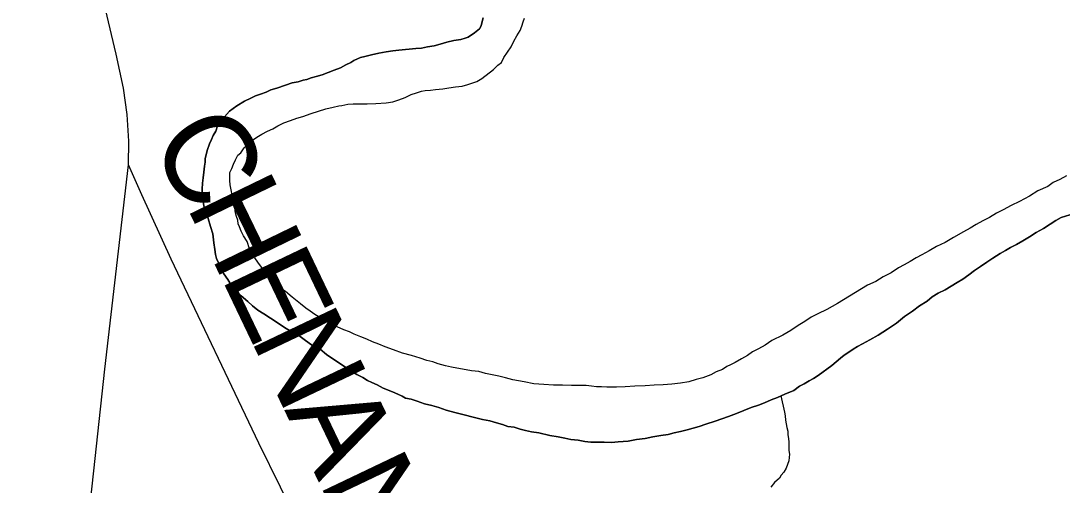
# Model space of a CAD drawing. Extents: x 0 to 34, y 0 to 22.
# Drawn here: x 4.269 to 4.921, y 16.776 to 17.067 of the extents above; entities that cross this region are included whole.
import ezdxf

# ---------------------------------------------------------------- set-up
doc = ezdxf.new("R2010")
doc.units = 0
for name, color, linetype in [('GM_X_Major_River', 7, 'Continuous'), ('GM_X_Minor_River', 7, 'Continuous'), ('GM_X_State_Route', 7, 'Continuous'), ('GM_X_Township_Road', 7, 'Continuous'), ('GM_X_Township_Road_Text', 7, 'Continuous')]:
    doc.layers.add(name, color=color, linetype=linetype)

msp = doc.modelspace()

# ---------------------------------------------------------------- linework, layer by layer
at = {"layer": 'GM_X_Major_River'}
for points in [[(4.55831, 17.06894), (4.55751, 17.06591), (4.55711, 17.06401), (4.55595, 17.06213), (4.55287, 17.05951), (4.54904, 17.05689), (4.54713, 17.05615), (4.54446, 17.05542), (4.53989, 17.05472), (4.5357, 17.05362), (4.5315, 17.05254), (4.52769, 17.05144), (4.5235, 17.05073), (4.51969, 17.05001), (4.51626, 17.04967), (4.50561, 17.04866), (4.5018, 17.04833), (4.49761, 17.04762), (4.49304, 17.04691), (4.48847, 17.04582), (4.48427, 17.04473), (4.4816, 17.044), (4.47969, 17.04326), (4.4774, 17.04215), (4.47548, 17.04104), (4.47243, 17.03955), (4.46898, 17.03769), (4.46516, 17.03622), (4.46134, 17.03474), (4.45752, 17.03326), (4.45371, 17.03217), (4.45066, 17.03144), (4.44798, 17.03034), (4.4457, 17.02998), (4.44265, 17.02888), (4.43884, 17.02817), (4.43464, 17.02669), (4.42929, 17.02486), (4.42548, 17.02376), (4.42242, 17.02228), (4.41898, 17.02118), (4.41593, 17.02007), (4.41287, 17.01859), (4.40905, 17.01673), (4.40407, 17.01375), (4.39947, 17.01039), (4.39639, 17.007), (4.39445, 17.00398), (4.39214, 17.00135), (4.39096, 16.99794), (4.3894, 16.9953), (4.38823, 16.99265), (4.38706, 16.99001), (4.38549, 16.98584), (4.38508, 16.98395), (4.38429, 16.98091), (4.38426, 16.97863), (4.38385, 16.97598), (4.38342, 16.97218), (4.383, 16.96877), (4.38258, 16.96535), (4.38254, 16.96155), (4.3825, 16.95851), (4.38355, 16.95127), (4.38465, 16.94746), (4.38612, 16.94326), (4.38758, 16.9383), (4.38904, 16.93372), (4.38973, 16.92801), (4.39044, 16.92382), (4.39079, 16.92078), (4.39151, 16.91811), (4.39262, 16.91543), (4.3941, 16.912), (4.39596, 16.90855), (4.39858, 16.9051)], [(4.39858, 16.9051), (4.39596, 16.90855), (4.3941, 16.912), (4.39262, 16.91543), (4.39151, 16.91811), (4.39079, 16.92078), (4.39044, 16.92382), (4.38973, 16.92801), (4.38904, 16.93372), (4.38758, 16.9383), (4.38612, 16.94326), (4.38465, 16.94746), (4.38355, 16.95127), (4.3825, 16.95851), (4.38254, 16.96155), (4.38258, 16.96535), (4.383, 16.96877), (4.38342, 16.97218), (4.38385, 16.97598), (4.38426, 16.97863), (4.38429, 16.98091), (4.38508, 16.98395), (4.38549, 16.98584), (4.38706, 16.99001), (4.38823, 16.99265), (4.3894, 16.9953), (4.39096, 16.99794), (4.39214, 17.00135), (4.39445, 17.00398), (4.39639, 17.007), (4.39947, 17.01039), (4.40407, 17.01375), (4.40905, 17.01673), (4.41287, 17.01859), (4.41593, 17.02007), (4.41898, 17.02118), (4.42242, 17.02228), (4.42548, 17.02376), (4.42929, 17.02486), (4.43464, 17.02669), (4.43884, 17.02817), (4.44265, 17.02888), (4.4457, 17.02998), (4.44798, 17.03034), (4.45066, 17.03144), (4.45371, 17.03217), (4.45752, 17.03326), (4.46134, 17.03474), (4.46516, 17.03622), (4.46898, 17.03769), (4.47243, 17.03955), (4.47548, 17.04104), (4.4774, 17.04215), (4.47969, 17.04326), (4.4816, 17.044), (4.48427, 17.04473), (4.48847, 17.04582), (4.49304, 17.04691), (4.49761, 17.04762), (4.5018, 17.04833), (4.50561, 17.04866), (4.51626, 17.04967), (4.51969, 17.05001), (4.5235, 17.05073), (4.52769, 17.05144), (4.5315, 17.05254), (4.5357, 17.05362), (4.53989, 17.05472), (4.54446, 17.05542), (4.54713, 17.05615), (4.54904, 17.05689), (4.55287, 17.05951), (4.55595, 17.06213), (4.55711, 17.06401), (4.55751, 17.06591), (4.55831, 17.06894)], [(4.51326, 17.02082), (4.51669, 17.02192), (4.51974, 17.02302), (4.52203, 17.02338), (4.52545, 17.02372), (4.5285, 17.02406), (4.53306, 17.02439), (4.53687, 17.0251), (4.54106, 17.02581), (4.54525, 17.02614), (4.54868, 17.02724), (4.55135, 17.02797), (4.55441, 17.02908), (4.55747, 17.03094), (4.56476, 17.03655), (4.56745, 17.03919), (4.56976, 17.04106), (4.57132, 17.04408), (4.57364, 17.04747), (4.57596, 17.05087), (4.57752, 17.05427), (4.57946, 17.05767), (4.5814, 17.06107), (4.58258, 17.06371), (4.58337, 17.06637), (4.58415, 17.06864)], [(4.51326, 17.02082), (4.51669, 17.02192), (4.51974, 17.02302), (4.52203, 17.02338), (4.52545, 17.02372), (4.5285, 17.02406), (4.53306, 17.02439), (4.53687, 17.0251), (4.54106, 17.02581), (4.54525, 17.02614), (4.54868, 17.02724), (4.55135, 17.02797), (4.55441, 17.02908), (4.55747, 17.03094), (4.56476, 17.03655), (4.56745, 17.03919), (4.56976, 17.04106), (4.57132, 17.04408), (4.57364, 17.04747), (4.57596, 17.05087), (4.57752, 17.05427), (4.57946, 17.05767), (4.5814, 17.06107), (4.58258, 17.06371), (4.58337, 17.06637), (4.58415, 17.06864)], [(4.62928, 16.83774), (4.62624, 16.83816), (4.62282, 16.83858), (4.61864, 16.83863), (4.6137, 16.83869), (4.608, 16.83875), (4.6023, 16.83882), (4.59622, 16.83927), (4.59015, 16.83973), (4.58408, 16.84094), (4.57687, 16.84216), (4.57232, 16.84336), (4.56815, 16.84455), (4.56398, 16.84536), (4.55981, 16.84617), (4.55564, 16.84736), (4.55109, 16.84779), (4.53857, 16.85022), (4.53478, 16.85103), (4.53023, 16.85222), (4.52683, 16.8534), (4.52303, 16.85421), (4.51887, 16.85578), (4.51357, 16.85736), (4.50789, 16.85895), (4.50221, 16.86092), (4.49691, 16.86288), (4.49313, 16.86444), (4.48897, 16.86601), (4.48556, 16.86758), (4.48178, 16.86914), (4.47762, 16.87071), (4.47459, 16.87227), (4.47119, 16.87345), (4.46703, 16.8754), (4.46287, 16.87735), (4.45909, 16.87929), (4.45608, 16.88123), (4.45306, 16.88317), (4.45004, 16.8851), (4.4474, 16.88704), (4.44401, 16.88974), (4.43874, 16.89398), (4.4346, 16.89745), (4.43084, 16.90092), (4.42746, 16.904), (4.42446, 16.90707), (4.42183, 16.91015), (4.41958, 16.91283), (4.41734, 16.9159), (4.41547, 16.91858), (4.41398, 16.92126), (4.41212, 16.92433), (4.41065, 16.9289), (4.40841, 16.93235), (4.40693, 16.93541), (4.40582, 16.93808), (4.40508, 16.94), (4.40473, 16.94228), (4.404, 16.94457), (4.40326, 16.94686), (4.40292, 16.9499), (4.4022, 16.95295), (4.40148, 16.95638), (4.40077, 16.96019), (4.40005, 16.96438), (4.39971, 16.96705), (4.39977, 16.97199), (4.40094, 16.97464), (4.40211, 16.97728), (4.40328, 16.97993), (4.40484, 16.98295), (4.40676, 16.98445), (4.40869, 16.98747), (4.41062, 16.98935), (4.41331, 16.99198), (4.41676, 16.99421), (4.41982, 16.99608), (4.42327, 16.99794), (4.42671, 16.99942), (4.42977, 17.00128), (4.43359, 17.00314), (4.43779, 17.00461), (4.44161, 17.00608), (4.44543, 17.00718), (4.45077, 17.00902), (4.45535, 17.01048), (4.45993, 17.01195), (4.4645, 17.01304), (4.46793, 17.01376), (4.46984, 17.01411), (4.47365, 17.01483), (4.47707, 17.01517), (4.48126, 17.01512), (4.48582, 17.01506), (4.49114, 17.01538), (4.49761, 17.01568), (4.5018, 17.01639), (4.50561, 17.01749), (4.50943, 17.01897), (4.51326, 17.02082)], [(4.62928, 16.83774), (4.62624, 16.83816), (4.62282, 16.83858), (4.61864, 16.83863), (4.6137, 16.83869), (4.608, 16.83875), (4.6023, 16.83882), (4.59622, 16.83927), (4.59015, 16.83973), (4.58408, 16.84094), (4.57687, 16.84216), (4.57232, 16.84336), (4.56815, 16.84455), (4.56398, 16.84536), (4.55981, 16.84617), (4.55564, 16.84736), (4.55109, 16.84779), (4.53857, 16.85022), (4.53478, 16.85103), (4.53023, 16.85222), (4.52683, 16.8534), (4.52303, 16.85421), (4.51887, 16.85578), (4.51357, 16.85736), (4.50789, 16.85895), (4.50221, 16.86092), (4.49691, 16.86288), (4.49313, 16.86444), (4.48897, 16.86601), (4.48556, 16.86758), (4.48178, 16.86914), (4.47762, 16.87071), (4.47459, 16.87227), (4.47119, 16.87345), (4.46703, 16.8754), (4.46287, 16.87735), (4.45909, 16.87929), (4.45608, 16.88123), (4.45306, 16.88317), (4.45004, 16.8851), (4.4474, 16.88704), (4.44401, 16.88974), (4.43874, 16.89398), (4.4346, 16.89745), (4.43084, 16.90092), (4.42746, 16.904), (4.42446, 16.90707), (4.42183, 16.91015), (4.41958, 16.91283), (4.41734, 16.9159), (4.41547, 16.91858), (4.41398, 16.92126), (4.41212, 16.92433), (4.41065, 16.9289), (4.40841, 16.93235), (4.40693, 16.93541), (4.40582, 16.93808), (4.40508, 16.94), (4.40473, 16.94228), (4.404, 16.94457), (4.40326, 16.94686), (4.40292, 16.9499), (4.4022, 16.95295), (4.40148, 16.95638), (4.40077, 16.96019), (4.40005, 16.96438), (4.39971, 16.96705), (4.39977, 16.97199), (4.40094, 16.97464), (4.40211, 16.97728), (4.40328, 16.97993), (4.40484, 16.98295), (4.40676, 16.98445), (4.40869, 16.98747), (4.41062, 16.98935), (4.41331, 16.99198), (4.41676, 16.99421), (4.41982, 16.99608), (4.42327, 16.99794), (4.42671, 16.99942), (4.42977, 17.00128), (4.43359, 17.00314), (4.43779, 17.00461), (4.44161, 17.00608), (4.44543, 17.00718), (4.45077, 17.00902), (4.45535, 17.01048), (4.45993, 17.01195), (4.4645, 17.01304), (4.46793, 17.01376), (4.46984, 17.01411), (4.47365, 17.01483), (4.47707, 17.01517), (4.48126, 17.01512), (4.48582, 17.01506), (4.49114, 17.01538), (4.49761, 17.01568), (4.5018, 17.01639), (4.50561, 17.01749), (4.50943, 17.01897), (4.51326, 17.02082)], [(4.92357, 16.96996), (4.91936, 16.96773), (4.91516, 16.96588), (4.91171, 16.96326), (4.90559, 16.96067), (4.90023, 16.95731), (4.89411, 16.95396), (4.88875, 16.95137), (4.88378, 16.94876), (4.87957, 16.94653), (4.87536, 16.94392), (4.87115, 16.94169), (4.86694, 16.93946), (4.86311, 16.93723), (4.85891, 16.93499), (4.85278, 16.93126), (4.84742, 16.92829), (4.84207, 16.92569), (4.83747, 16.92308), (4.83288, 16.92048), (4.82944, 16.91862), (4.82561, 16.91638), (4.82178, 16.91415), (4.81834, 16.91229), (4.81374, 16.9093), (4.80877, 16.9067), (4.80417, 16.90371), (4.79882, 16.90149), (4.78006, 16.88993), (4.77355, 16.88621), (4.76782, 16.88362), (4.76361, 16.88139), (4.75977, 16.87877), (4.75556, 16.87616), (4.75096, 16.87317), (4.74599, 16.87019), (4.7391, 16.86685), (4.73489, 16.86386), (4.73068, 16.86163), (4.72685, 16.85977), (4.72379, 16.85753), (4.71996, 16.85529), (4.71613, 16.85306), (4.71307, 16.85157), (4.71078, 16.85046), (4.70809, 16.84859), (4.70427, 16.84712), (4.70083, 16.84526), (4.69587, 16.84342), (4.69167, 16.84232), (4.68709, 16.84086), (4.68176, 16.84016), (4.67643, 16.83946), (4.67111, 16.83915), (4.6654, 16.83883), (4.6597, 16.83852), (4.65323, 16.83822), (4.64714, 16.83791), (4.64182, 16.83759), (4.63574, 16.83766), (4.63231, 16.83771), (4.62928, 16.83774)], [(4.92357, 16.96996), (4.91936, 16.96773), (4.91516, 16.96588), (4.91171, 16.96326), (4.90559, 16.96067), (4.90023, 16.95731), (4.89411, 16.95396), (4.88875, 16.95137), (4.88378, 16.94876), (4.87957, 16.94653), (4.87536, 16.94392), (4.87115, 16.94169), (4.86694, 16.93946), (4.86311, 16.93723), (4.85891, 16.93499), (4.85278, 16.93126), (4.84742, 16.92829), (4.84207, 16.92569), (4.83747, 16.92308), (4.83288, 16.92048), (4.82944, 16.91862), (4.82561, 16.91638), (4.82178, 16.91415), (4.81834, 16.91229), (4.81374, 16.9093), (4.80877, 16.9067), (4.80417, 16.90371), (4.79882, 16.90149), (4.78006, 16.88993), (4.77355, 16.88621), (4.76782, 16.88362), (4.76361, 16.88139), (4.75977, 16.87877), (4.75556, 16.87616), (4.75096, 16.87317), (4.74599, 16.87019), (4.7391, 16.86685), (4.73489, 16.86386), (4.73068, 16.86163), (4.72685, 16.85977), (4.72379, 16.85753), (4.71996, 16.85529), (4.71613, 16.85306), (4.71307, 16.85157), (4.71078, 16.85046), (4.70809, 16.84859), (4.70427, 16.84712), (4.70083, 16.84526), (4.69587, 16.84342), (4.69167, 16.84232), (4.68709, 16.84086), (4.68176, 16.84016), (4.67643, 16.83946), (4.67111, 16.83915), (4.6654, 16.83883), (4.6597, 16.83852), (4.65323, 16.83822), (4.64714, 16.83791), (4.64182, 16.83759), (4.63574, 16.83766), (4.63231, 16.83771), (4.62928, 16.83774)], [(4.82215, 16.88183), (4.82714, 16.88519), (4.83136, 16.88856), (4.83634, 16.89155), (4.83941, 16.89417), (4.84324, 16.8964), (4.84745, 16.89864), (4.85127, 16.90087), (4.8551, 16.90311), (4.85855, 16.90535), (4.86238, 16.90796), (4.86584, 16.91058), (4.86967, 16.9132), (4.8735, 16.91581), (4.87733, 16.91843), (4.88193, 16.92141), (4.88537, 16.92328), (4.88844, 16.92514), (4.89226, 16.927), (4.89609, 16.92923), (4.9003, 16.93184), (4.90452, 16.93445), (4.90911, 16.93706), (4.91332, 16.93967), (4.91677, 16.94191), (4.92021, 16.94377), (4.92556, 16.94561)], [(4.92556, 16.94561), (4.92021, 16.94377), (4.91677, 16.94191), (4.91332, 16.93967), (4.90911, 16.93706), (4.90452, 16.93445), (4.9003, 16.93184), (4.89609, 16.92923), (4.89226, 16.927), (4.88844, 16.92514), (4.88537, 16.92328), (4.88193, 16.92141), (4.87733, 16.91843), (4.8735, 16.91581), (4.86967, 16.9132), (4.86584, 16.91058), (4.86238, 16.90796), (4.85855, 16.90535), (4.8551, 16.90311), (4.85127, 16.90087), (4.84745, 16.89864), (4.84324, 16.8964), (4.83941, 16.89417), (4.83634, 16.89155), (4.83136, 16.88856), (4.82714, 16.88519), (4.82215, 16.88183)], [(4.39858, 16.9051), (4.40082, 16.90127), (4.40344, 16.8982), (4.40682, 16.89474), (4.41096, 16.89127), (4.41397, 16.88857), (4.41736, 16.88587), (4.42113, 16.88355), (4.42528, 16.88083), (4.42943, 16.87812), (4.43395, 16.87503), (4.43848, 16.87231), (4.44302, 16.86998), (4.44716, 16.86689), (4.45093, 16.86419), (4.45622, 16.86146), (4.46036, 16.85799), (4.46488, 16.8549), (4.46903, 16.85219), (4.47242, 16.84987), (4.47582, 16.84755), (4.47922, 16.8456), (4.48299, 16.84366), (4.48601, 16.84172), (4.48866, 16.84055), (4.49206, 16.83899), (4.49584, 16.83704), (4.50151, 16.8347), (4.50491, 16.83313), (4.50756, 16.83196), (4.50983, 16.8308), (4.51324, 16.82999), (4.51703, 16.82881), (4.52157, 16.82723), (4.52612, 16.82604), (4.53066, 16.82485), (4.53521, 16.82327), (4.54051, 16.82169), (4.55794, 16.8173), (4.5625, 16.81649), (4.56666, 16.8153), (4.57045, 16.81411), (4.57386, 16.81293), (4.57765, 16.81251), (4.58144, 16.81132), (4.58485, 16.81052), (4.58864, 16.80972), (4.59319, 16.8089), (4.60002, 16.8073), (4.60533, 16.80648), (4.6095, 16.80567), (4.61329, 16.80486), (4.61785, 16.80443), (4.62202, 16.80362), (4.62582, 16.80319), (4.63, 16.80314), (4.63418, 16.80309), (4.63874, 16.80304), (4.64293, 16.80337), (4.64901, 16.80368), (4.65435, 16.80475), (4.65968, 16.80545), (4.66463, 16.80653), (4.66958, 16.80723), (4.67415, 16.80794), (4.67797, 16.80904), (4.68178, 16.80975), (4.68597, 16.81084), (4.68979, 16.81194), (4.6936, 16.81303), (4.6978, 16.8145), (4.70352, 16.81633), (4.70772, 16.8178), (4.71192, 16.81928), (4.71689, 16.82112), (4.72147, 16.82296), (4.72605, 16.82481), (4.73063, 16.82628), (4.73445, 16.82775), (4.73866, 16.8296), (4.74247, 16.83108), (4.74706, 16.8333), (4.75279, 16.83552), (4.75625, 16.83814), (4.7593, 16.83962), (4.76237, 16.84148), (4.76505, 16.84298), (4.76811, 16.84484), (4.77655, 16.8512), (4.77924, 16.85345), (4.78193, 16.8557), (4.78423, 16.85757), (4.78729, 16.85944), (4.78997, 16.86131), (4.79266, 16.86317), (4.79572, 16.86466), (4.80031, 16.86726), (4.80567, 16.87024), (4.81142, 16.87398), (4.81716, 16.87771), (4.82215, 16.88183)], [(4.82215, 16.88183), (4.81716, 16.87771), (4.81142, 16.87398), (4.80567, 16.87024), (4.80031, 16.86726), (4.79572, 16.86466), (4.79266, 16.86317), (4.78997, 16.86131), (4.78729, 16.85944), (4.78423, 16.85757), (4.78193, 16.8557), (4.77924, 16.85345), (4.77655, 16.8512), (4.76811, 16.84484), (4.76505, 16.84298), (4.76237, 16.84148), (4.7593, 16.83962), (4.75625, 16.83814), (4.75279, 16.83552), (4.74706, 16.8333), (4.74247, 16.83108), (4.73866, 16.8296), (4.73445, 16.82775), (4.73063, 16.82628), (4.72605, 16.82481), (4.72147, 16.82296), (4.71689, 16.82112), (4.71192, 16.81928), (4.70772, 16.8178), (4.70352, 16.81633), (4.6978, 16.8145), (4.6936, 16.81303), (4.68979, 16.81194), (4.68597, 16.81084), (4.68178, 16.80975), (4.67797, 16.80904), (4.67415, 16.80794), (4.66958, 16.80723), (4.66463, 16.80653), (4.65968, 16.80545), (4.65435, 16.80475), (4.64901, 16.80368), (4.64293, 16.80337), (4.63874, 16.80304), (4.63418, 16.80309), (4.63, 16.80314), (4.62582, 16.80319), (4.62202, 16.80362), (4.61785, 16.80443), (4.61329, 16.80486), (4.6095, 16.80567), (4.60533, 16.80648), (4.60002, 16.8073), (4.59319, 16.8089), (4.58864, 16.80972), (4.58485, 16.81052), (4.58144, 16.81132), (4.57765, 16.81251), (4.57386, 16.81293), (4.57045, 16.81411), (4.56666, 16.8153), (4.5625, 16.81649), (4.55794, 16.8173), (4.54051, 16.82169), (4.53521, 16.82327), (4.53066, 16.82485), (4.52612, 16.82604), (4.52157, 16.82723), (4.51703, 16.82881), (4.51324, 16.82999), (4.50983, 16.8308), (4.50756, 16.83196), (4.50491, 16.83313), (4.50151, 16.8347), (4.49584, 16.83704), (4.49206, 16.83899), (4.48866, 16.84055), (4.48601, 16.84172), (4.48299, 16.84366), (4.47922, 16.8456), (4.47582, 16.84755), (4.47242, 16.84987), (4.46903, 16.85219), (4.46488, 16.8549), (4.46036, 16.85799), (4.45622, 16.86146), (4.45093, 16.86419), (4.44716, 16.86689), (4.44302, 16.86998), (4.43848, 16.87231), (4.43395, 16.87503), (4.42943, 16.87812), (4.42528, 16.88083), (4.42113, 16.88355), (4.41736, 16.88587), (4.41397, 16.88857), (4.41096, 16.89127), (4.40682, 16.89474), (4.40344, 16.8982), (4.40082, 16.90127), (4.39858, 16.9051)]]:
    msp.add_lwpolyline(points, dxfattribs=at)
at = {"layer": 'GM_X_Minor_River'}
msp.add_lwpolyline([(4.74463, 16.83212), (4.74693, 16.8219), (4.74728, 16.81962), (4.74763, 16.81695), (4.74798, 16.81467), (4.74833, 16.81238), (4.74906, 16.81009), (4.74904, 16.80781), (4.74939, 16.80553), (4.74974, 16.80324), (4.74971, 16.80058), (4.74968, 16.79792), (4.75003, 16.79564), (4.7496, 16.79146), (4.74802, 16.78692), (4.74647, 16.78428), (4.74493, 16.78239), (4.74377, 16.78051), (4.74069, 16.77788), (4.73838, 16.77487)], dxfattribs=at)
at = {"layer": 'GM_X_State_Route'}
msp.add_lwpolyline([(4.27027, 16.37631), (4.28475, 16.50856), (4.30229, 16.67131), (4.32159, 16.84896), (4.33629, 16.97683), (4.33651, 16.99175), (4.33541, 17.00842), (4.33322, 17.02486), (4.32861, 17.04614), (4.2944, 17.1909), (4.28409, 17.24968), (4.25492, 17.42119), (4.23825, 17.5234), (4.22575, 17.62977), (4.2229, 17.65346), (4.21763, 17.68154), (4.20535, 17.73834), (4.16981, 17.88475)], dxfattribs=at)
at = {"layer": 'GM_X_Township_Road'}
msp.add_lwpolyline([(4.65016, 16.36992), (4.61886, 16.40425), (4.59207, 16.43209), (4.5868, 16.43819), (4.58417, 16.4439), (4.5808, 16.45227), (4.57745, 16.46482), (4.57521, 16.47318), (4.56771, 16.49031), (4.50127, 16.62771), (4.44309, 16.75065), (4.43145, 16.77501), (4.41794, 16.80242), (4.36314, 16.91774), (4.34476, 16.95808), (4.33629, 16.97683)], dxfattribs=at)

# ---------------------------------------------------------------- texts
at = {"layer": 'GM_X_Township_Road_Text'}
for s, rotation, p in [('C', 301.63512, (4.34833, 16.99023)), ('H', 295.88245, (4.37208, 16.95182)), ('E', 295.53005, (4.39387, 16.90692)), ('N', 295.5191, (4.41219, 16.86857)), ('A', 295.5222, (4.43373, 16.82345)), ('N', 295.52807, (4.45527, 16.77832))]:
    msp.add_text(s, height=0.05682, rotation=rotation, dxfattribs=at).set_placement(p)

doc.saveas('drawing.dxf')
